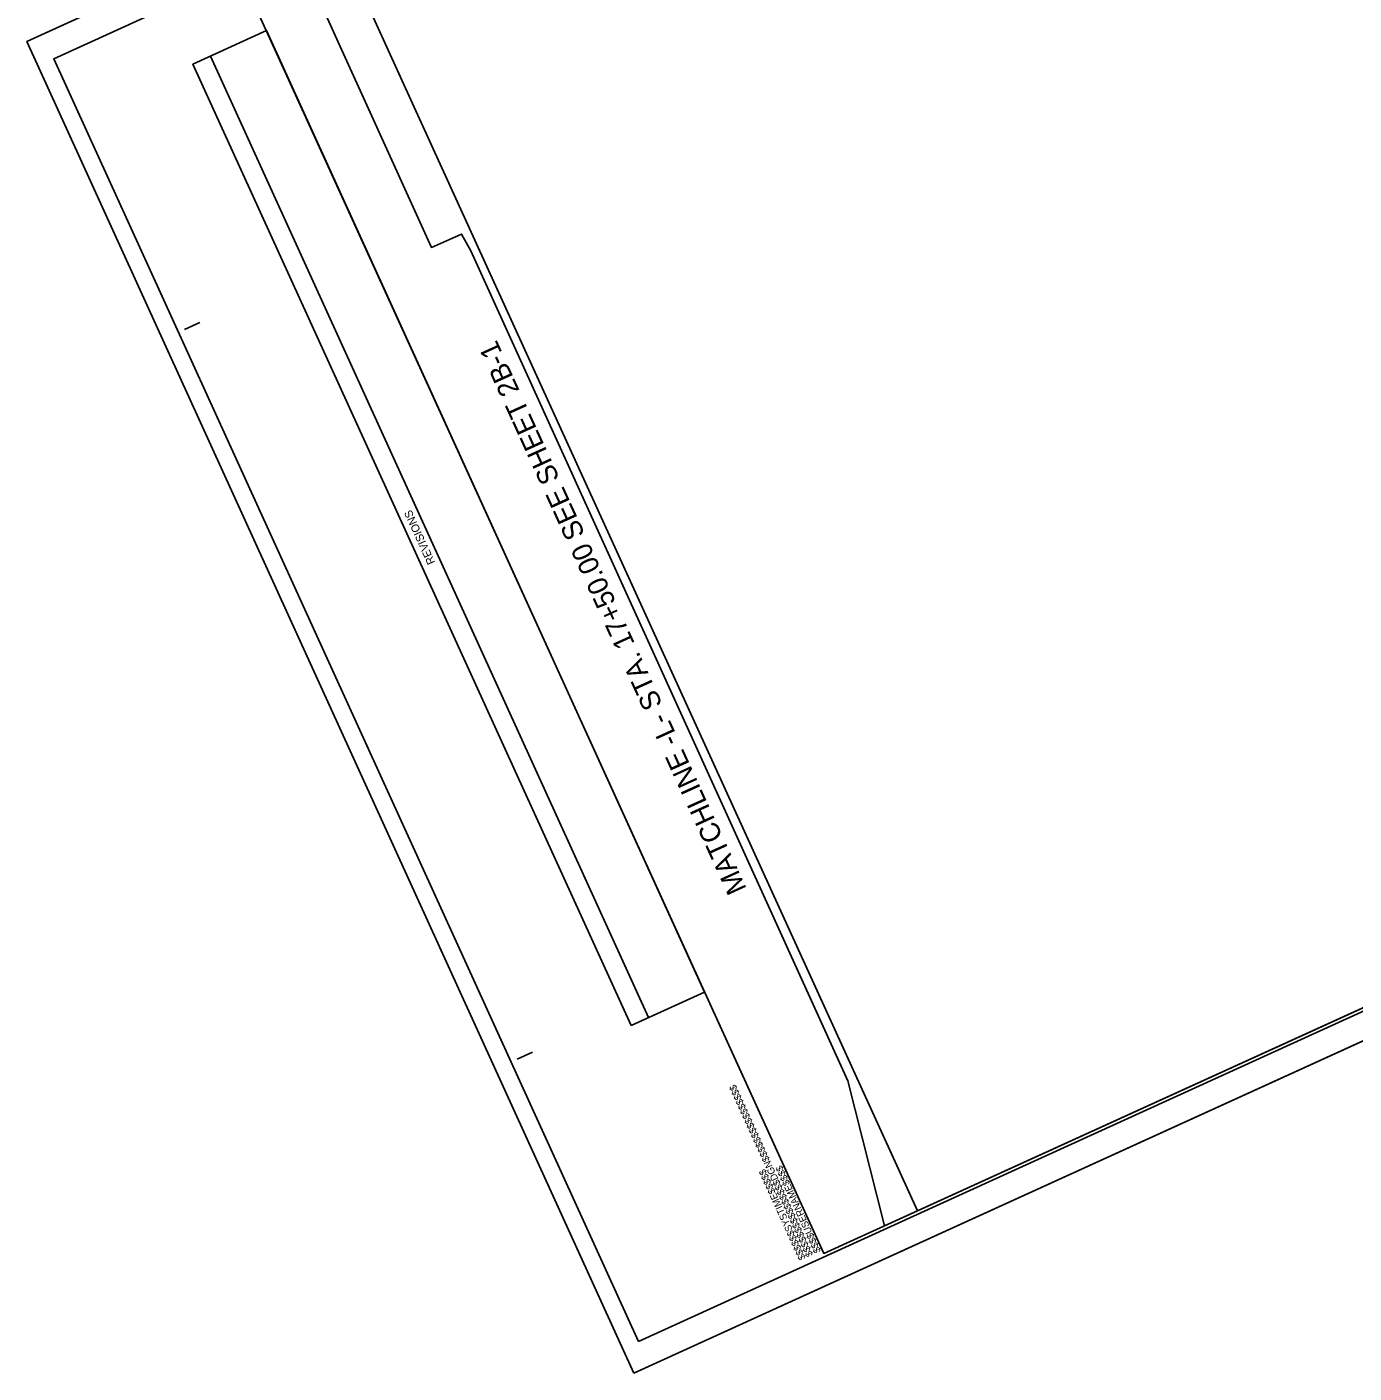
# Model space of a CAD drawing. Extents: x 2247910 to 2249896, y 662531 to 664300.
# Drawn here: x 2247910 to 2248903, y 662531 to 663539 of the extents above; entities that cross this region are included whole.
import ezdxf

# ---------------------------------------------------------------- set-up
doc = ezdxf.new("R2010")
doc.units = 0
for name, color, linetype in [('Matchline', 7, 'Continuous'), ('Matchline Text', 7, 'Continuous'), ('Sheet Block Revision CELL', 7, 'Continuous'), ('Sheet Clip Boundary CELL', 7, 'Continuous'), ('Sheet Cutting Line CELL', 7, 'Continuous'), ('Sheet Layout Plan Border', 7, 'Continuous'), ('Sheet Plan CELL', 7, 'Continuous'), ('Sheet Plan Layout CELL', 7, 'Continuous'), ('Sheet Plot Border Inside CELL', 7, 'Continuous'), ('Sheet Plot Border Outside CELL', 7, 'Continuous')]:
    doc.layers.add(name, color=color, linetype=linetype)

msp = doc.modelspace()

# ---------------------------------------------------------------- linework, layer by layer
at = {"layer": 'Matchline'}
msp.add_line((2248241.7, 663371.1), (2248523.8, 662750), dxfattribs=at)
at = {"layer": 'Sheet Block Revision CELL'}
msp.add_line((2248374.7, 662797.4), (2248046.9, 663516.9), dxfattribs=at)
msp.add_lwpolyline([(2248361.5, 662791.4), (2248033.7, 663510.8), (2248088.7, 663536), (2248416.6, 662816.5)], close=True, dxfattribs=at)
at = {"layer": 'Sheet Clip Boundary CELL'}
msp.add_lwpolyline([(2248112.3, 663594.1), (2248115.5, 663587), (2248212.2, 663373.7), (2248234.7, 663383.7), (2248241.7, 663371.1), (2248523.8, 662750), (2248551.2, 662641.6), (2249638.1, 663136.9), (2249825.2, 663222.1), (2249759.4, 663344.8), (2249697.6, 663317.2), (2249673.4, 663362.4), (2249425.3, 663908.7), (2249477.5, 663985.1), (2249333.3, 663919.4), (2249245.6, 664111.9), (2248806.2, 663911.3), (2248826.4, 663857), (2248820.5, 663848.4), (2248540.8, 663728.2), (2248517.3, 663777.9), (2248115.8, 663597.1)], close=True, dxfattribs=at)
at = {"layer": 'Sheet Cutting Line CELL'}
for p, q in [((2249441.4, 664225.8), (2247909.5, 663527.8)), ((2247909.5, 663527.8), (2248363.6, 662531.3)), ((2248363.6, 662531.3), (2249895.5, 663229.4))]:
    msp.add_line(p, q, dxfattribs=at)
at = {"layer": 'Sheet Layout Plan Border'}
msp.add_lwpolyline([(2248198.1, 663481.5), (2248575.8, 662652.8), (2249849.7, 663233.3), (2249502.1, 663996.3), (2249329.8, 663917.8), (2249242.1, 664110.3), (2248140.4, 663608.2)], close=True, dxfattribs=at)
at = {"layer": 'Sheet Plan CELL'}
for p, q in [((2248027.5, 663312.3), (2248038.8, 663317.5)), ((2248276.3, 662766.3), (2248287.7, 662771.5)), ((2248505.7, 662620.9), (2248505.7, 662620.9))]:
    msp.add_line(p, q, dxfattribs=at)
for points in [[(2249435.3, 664198.3), (2248070.3, 663576.3), (2248505.7, 662620.9), (2249870.7, 663242.8)], [(2248505.7, 662620.9), (2248070.3, 663576.3), (2249253.3, 664115.4), (2249315.5, 663978.8), (2249497.5, 664061.8), (2249870.7, 663242.8)]]:
    msp.add_lwpolyline(points, close=True, dxfattribs=at)
at = {"layer": 'Sheet Plan Layout CELL'}
msp.add_lwpolyline([(2248070.3, 663576.3), (2248505.7, 662620.9), (2249870.7, 663242.8), (2249523, 664005.9), (2249305.3, 663906.7), (2249217.6, 664099.1)], close=True, dxfattribs=at)
at = {"layer": 'Sheet Plot Border Inside CELL'}
msp.add_lwpolyline([(2248367.1, 662554.9), (2249883.1, 663245.8), (2249445.6, 664205.8), (2247929.6, 663514.9)], close=True, dxfattribs=at)
at = {"layer": 'Sheet Plot Border Outside CELL'}
msp.add_lwpolyline([(2248363.6, 662531.3), (2249895.5, 663229.4), (2249441.4, 664225.8), (2247909.5, 663527.8)], close=True, dxfattribs=at)

# ---------------------------------------------------------------- texts
at = {"layer": 'Matchline Text'}
msp.add_text('MATCHLINE -L- STA. 17+50.00 SEE SHEET 2B-1', height=15, rotation=114.4979, dxfattribs=at).set_placement((2248448.2, 662893.7))
at = {"layer": 'Sheet Block Revision CELL'}
msp.add_text('REVISIONS', height=6, rotation=114.4979, dxfattribs=at).set_placement((2248215.1, 663138))
at = {"layer": 'Sheet Plan CELL'}
for s, p in [('$$$$$$$$$$$$$$$$DGN$$$$$$$$$$$$$$$$', (2248497.8, 662619.8)), ('$$$$USERNAME$$$$', (2248503.7, 662622.6)), ('$$$$$$SYSTIME$$$$$', (2248492.3, 662617.3))]:
    msp.add_text(s, height=5.25, rotation=114.4979, dxfattribs=at).set_placement(p)

doc.saveas('drawing.dxf')
